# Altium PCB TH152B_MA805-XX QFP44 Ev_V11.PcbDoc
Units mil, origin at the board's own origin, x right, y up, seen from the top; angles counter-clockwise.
Board outline 2850 x 2380 mil, 2 copper layers (Top Layer, Bottom Layer); 48 components, 65 nets, 282 pads, 145 vias.
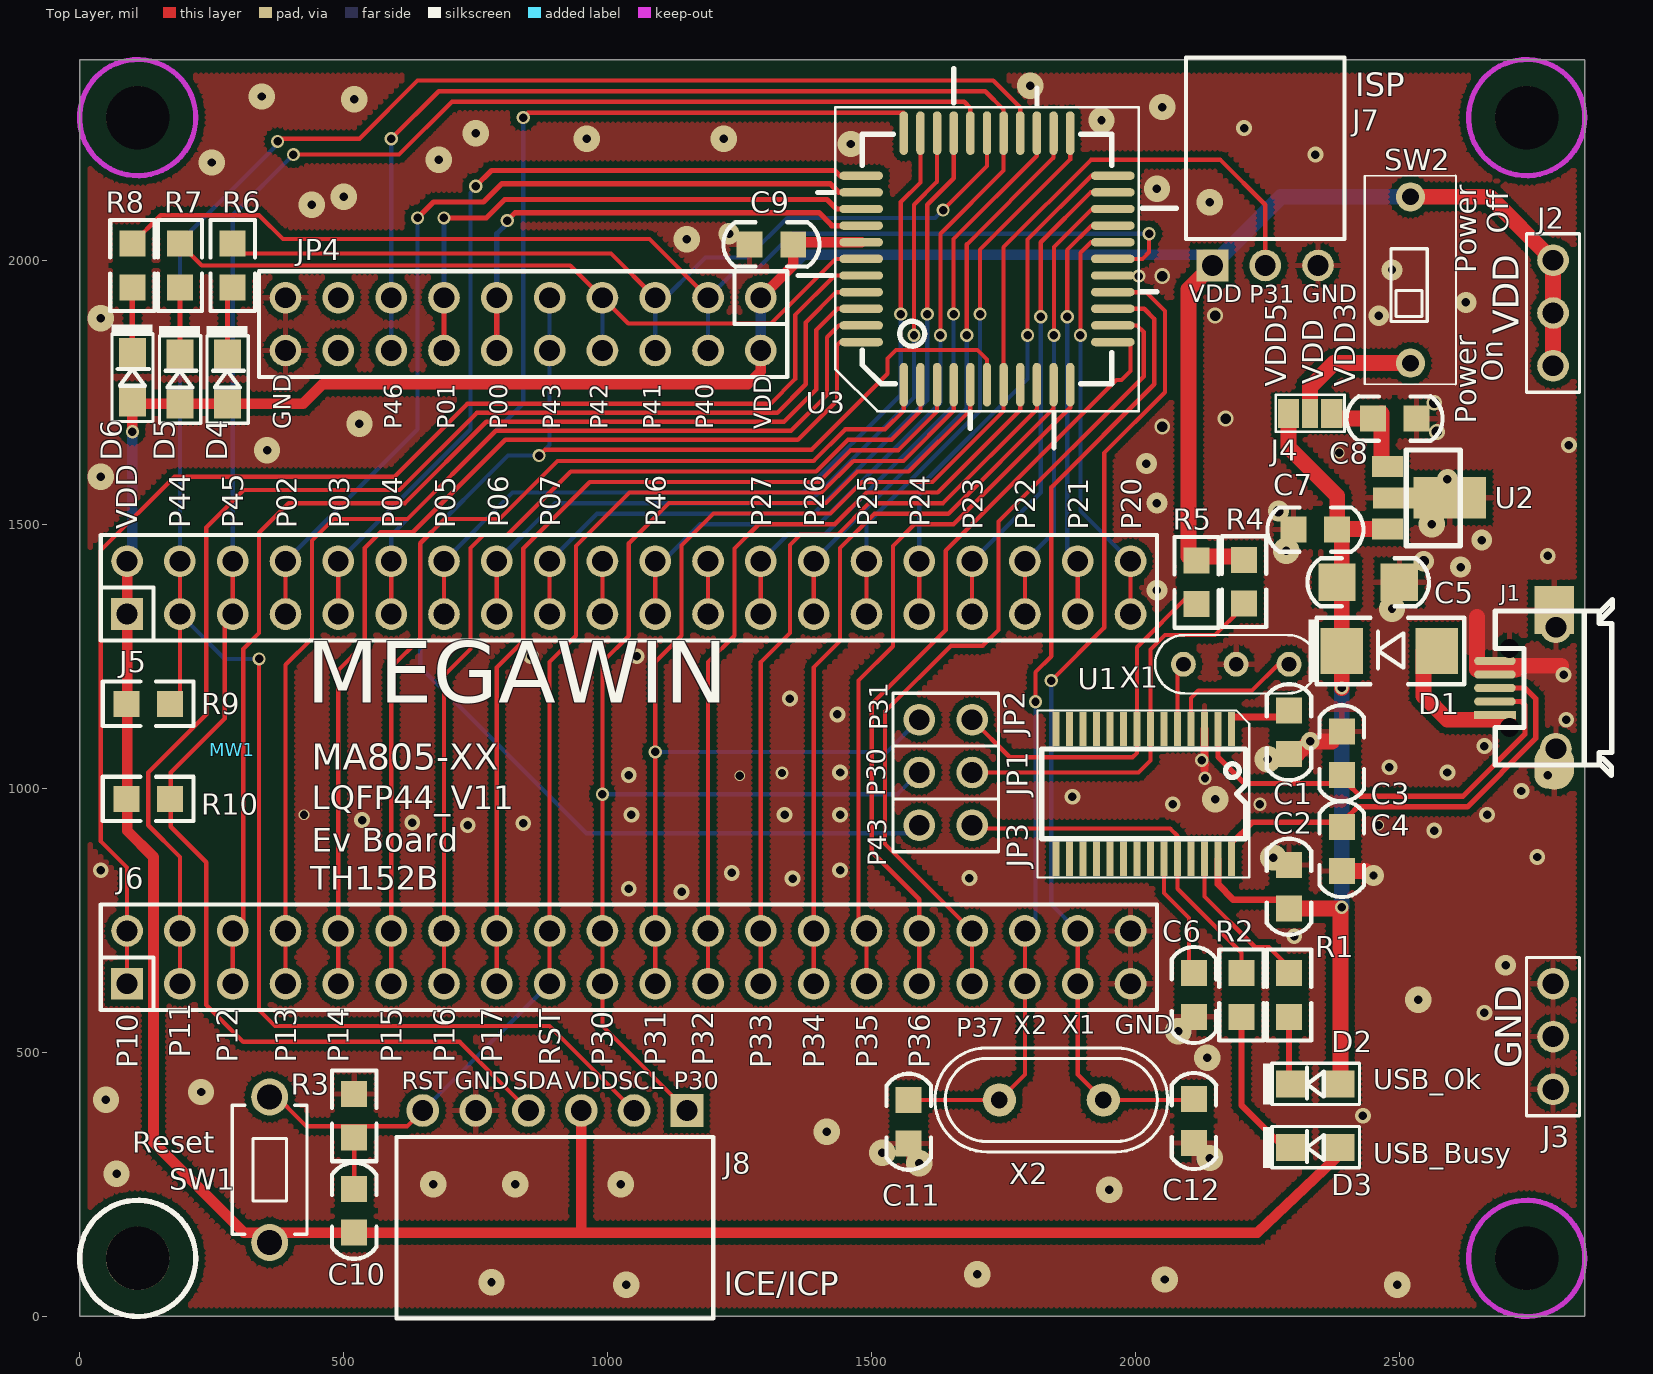
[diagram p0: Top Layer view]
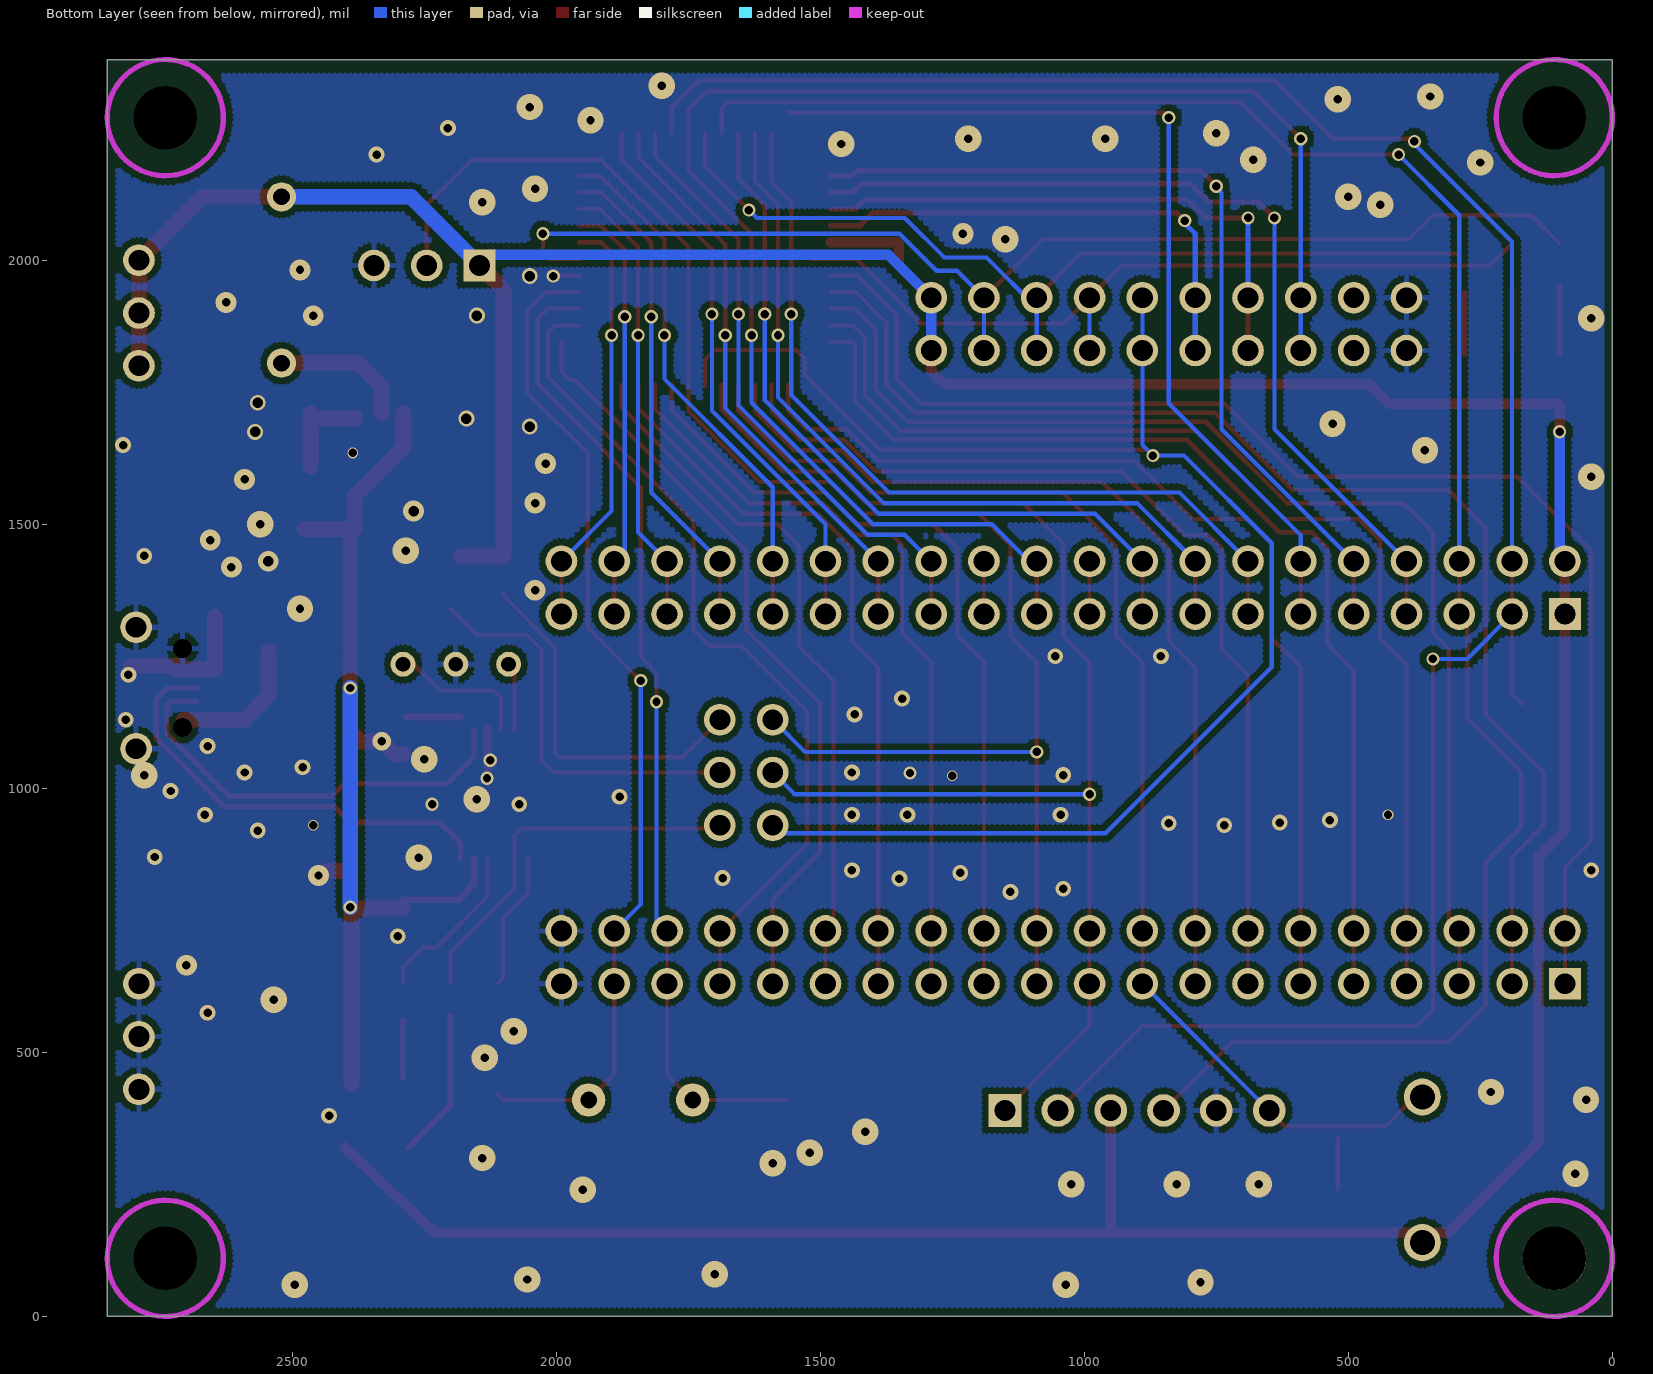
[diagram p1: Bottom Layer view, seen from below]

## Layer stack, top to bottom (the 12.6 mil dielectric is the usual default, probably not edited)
Top Layer: signal copper 1.4
Dielectric: dielectric 12.6, FR-4, Dk 4.8
Bottom Layer: signal copper 1.4

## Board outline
0,0 0,2380 2850,2380 2850,0

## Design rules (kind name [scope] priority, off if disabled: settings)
Clearance 12 [All] p1 off: gap=12
Clearance 10 [All] p2 off: gap=10
Clearance 6 [All] p3: gap=6
ComponentClearance [All] p1 off: gap=10 collisioncheckmode=3 verticalgap=10 showdistances=FALSE
HoleSize [All] p1: absolutevalues=TRUE maxlimit=500 minlimit=1 maxpercent=80.000 minpercent=20.000
MinimumSolderMaskSliver [All] p1 off: minsoldermaskwidth=10
PolygonConnect VIA [ISVIA] p1: connectstyle=Direct reliefconductorwidth=10 reliefentries=4 polygonreliefangle="90 Angle"
PolygonConnect [All] p2: connectstyle=Relief reliefconductorwidth=10 reliefentries=4 polygonreliefangle="90 Angle"
RoutingVias [All] p1: holewidth=16 width=25 viastyle="Through Hole" minholewidth=16 minwidth=24 maxholewidth=28 maxwidth=50
SilkToSilkClearance [All] p1 off: silktosilkclearance=10
SilkscreenOverComponentPads [All] p1 off: minsilkscreentomaskgap=10
SolderMaskExpansion [All] p1 off: expansion=4
Width [All] p1: maxlimit=200 minlimit=6 preferedwidth=10
23 further rules are at their usual default settings.

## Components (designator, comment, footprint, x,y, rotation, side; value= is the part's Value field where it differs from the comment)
C1 "4.7uF" 0805C 2290,1106.34 r270 top
C2 "0.1uF" 0805C 2290,813.66 r270 top
C3 "15pF" 0805C 2390,1066.34 r90 top
C4 "15pF" 0805C 2390,885 r270 top
C5 "4.7uF" 1206C 2440,1390 r0 top
C6 "0.1uF" 0805C 2110,608.66 r90 top
C7 "0.1uF" 0805C 2340,1490 r180 top
C8 "4.7uF" 0805C 2490,1700 r0 top
C9 "0.1uF" 0805C 1310,2030 r180 top
C10 "1u" 0805C 520,200 r90 top
C11 "NC" 0805C 1570,368.66 r270 top
C12 "NC" 0805C 2110,370 r270 top
D1 "1N5817" D5817_SMD_1 2480,1260 r0 top
D2 "Yellow" 0805D 2340,440 r180 top
D3 "RED" 0805D 2340,320 r180 top
D4 "Green" 0805D 280,1775 r90 top
D5 "RED" 0805D 190,1775 r90 top
D6 "Green" 0805D 100,1778.08 r90 top
J1 "Micro USB母座" JACK_USB_SMD290X220P065 2680,1190 r180 top
J2 "*" PS3P254 2790,1800 r90 top
J3 "*" PS3P254 2790,430 r90 top
J4 "*" JUMP3_SMD 2330,1710 r0 top
J5 "*" PS20X2P254 90,1330 r0 top locked
J6 "*" PS20X2P254 90,630 r0 top
J7 "*" PS3P254f_90 2145,1990 r0 top
J8 "*" PS6P254F_90 1150,390 r180 top
JP1 "JUMPER2" PS2P254 1590,1030 r0 top
JP2 "JUMPER2" PS2P254 1590,1130 r0 top
JP3 "JUMPER2" PS2P254 1590,930 r0 top
JP4 "*" PS10X2P254 1290,1929 r180 top
MW1 "MW-A4" MEGAWIN_T 289.19,1073.04 r0 top
R1 "1K" 0805R 2290,608.66 r270 top
R2 "1K" 0805R 2200,608.66 r270 top
R3 "47K" 0805R 520,380 r270 top
R4 "4.7K" 0805R 2205,1391.34 r270 top
R5 "4.7K" 0805R 2115,1390 r270 top
R6 "1K" 0805R 290,1990 r270 top
R7 "1K" 0805R 190,1990 r270 top
R8 "1K" 0805R 100,1990 r270 top
R9 "4.7K" 0805R 130,1160 r180 top
R10 "4.7K" 0805R 130,980 r180 top
SW1 "SW TACT-SPST" SW_T_2P 360,277.79 r90 top
SW2 "-" DIP2_SW 2520,1805.04 r90 top
U1 "MA101_TSSOP28" TSSOP28_170P065 2014.84,989.52 r180 top
U2 "AIC1734-33(SOT-89)" SOT89 2476.38,1550 r270 top
U3 "MA805-XX  LQFP44" QFP44_10X10P080 1560.71,1764.31 r90 top locked
X1 "6MHz" X3P 2290,1235 r180 top
X2 "NC" X49U 1840,410 r0 top

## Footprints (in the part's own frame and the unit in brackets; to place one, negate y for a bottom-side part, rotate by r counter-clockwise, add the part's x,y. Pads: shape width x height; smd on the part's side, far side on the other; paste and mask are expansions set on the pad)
0805C [mm]
  rect 1.25x1.25 smd: 1(-1.05,0) 2(1.05,0)
  silkscreen extent -2.31,-1.07 2.31,1.07
0805D [mm]
  rect 1.4x1.3 smd: 1(-1.192,0) 2(1.192,0)
  silkscreen extent -2.12,-1 2.53,0.98
0805R [mm]
  rect 1.25x1.25 smd: 1(-1.05,0) 2(1.05,0)
  silkscreen extent -2.18,-1.07 2.18,1.07
1206C [mm]
  rect 1.8x1.8 smd: 1(-1.5,0) 2(1.5,0)
  silkscreen extent -2.92,-1.15 2.92,1.16
D5817_SMD_1 [mil]
  rect 80x86.61 smd: 1(90,0) 2(-90,0)
  silkscreen extent -153,-63 142,63
DIP2_SW [mm]
  round 1.4 hole 0.8: 1(0,0) 2(8,0)
  silkscreen extent -1.02,-2.2 9.02,2.2
JACK_USB_SMD290X220P065 [mm]
  rect 1.9x1.8 on Mech2: 0(-2.85,-1.15) 0(-2.85,1.15)
  round 0.8 hole 0.9 unplated: 1(-0.7,1.9) 5(-0.7,-1.9)
  rect 2x0.4 smd: 1(0,1.3)
  oval 2x0.4 smd: 2(0,0.65) 3(0,0) 4(0,-0.65) 5(0,-1.3)
  round 1.524 hole 1: 5(-2.931,2.921) 5(-2.931,-2.921)
  oval 1.9x2.3 smd: 5(-2.85,3.75)
  rect 1.9x2.3 smd: 5(-2.85,-3.75)
  silkscreen extent -5.65,-4.25 -0.01,4.2
JUMP3_SMD [mil]
  rect 40x55 smd: 1(-41,0) 3(41,0)
  rect 30x55 smd: 2(0,0)
  silkscreen extent -65,-35 65,35
MEGAWIN_T [mil]
PS2P254 [mil]
  round 60 hole 39.37: 1(0,0) 2(100,0)
  silkscreen extent -50,-50 150,50
PS3P254 [mil]
  round 60 hole 39.37: 1(0,0) 2(100,0) 3(200,0)
  silkscreen extent -50,-50 250,50
PS3P254f_90 [mil]
  rect 60x60 hole 39.37: 1(0,0)
  round 60 hole 39.37: 2(100,0) 3(200,0)
  silkscreen extent -50,50 250,394
PS6P254F_90 [mil]
  rect 62x62 hole 39.37: 1(0,0)
  round 62 hole 39.37: 2(100,0) 3(200,0) 4(300,0) 5(400,0) 6(500,0)
  silkscreen extent -50,50 550,394
PS10X2P254 [mil]
  round 60 hole 39.37: 1(0,0) 2(0,100) 3(100,0) 4(100,100) 5(200,0) 6(200,100) 7(300,0) 8(300,100) 9(400,0) 10(400,100) 11(500,0) 12(500,100) 13(600,0) 14(600,100) 15(700,0) 16(700,100) 17(800,0) 18(800,100) 19(900,0) 20(900,100)
  silkscreen extent -50,-50 950,150
PS20X2P254 [mil]
  rect 60x60 hole 39.37: 1(0,0)
  round 60 hole 39.37: 2(0,100) 3(100,0) 4(100,100) 5(200,0) 6(200,100) 7(300,0) 8(300,100) 9(400,0) 10(400,100) 11(500,0) 12(500,100) 13(600,0) 14(600,100) 15(700,0) 16(700,100) 17(800,0) 18(800,100) 19(900,0) 20(900,100) 21(1000,0) 22(1000,100) 23(1100,0) 24(1100,100) 25(1200,0) 26(1200,100) 27(1300,0) 28(1300,100) 29(1400,0) 30(1400,100) 31(1500,0) 32(1500,100) 33(1600,0) 34(1600,100) 35(1700,0) 36(1700,100) 37(1800,0) 38(1800,100) 39(1900,0) 40(1900,100)
  silkscreen extent -50,-50 1950,150
QFP44_10X10P080 [mm]
  oval 2.1x0.406 smd: 1(0,0) 2(0,-0.8) 3(0,-1.6) 4(0,-2.4) 5(0,-3.2) 6(0,-4) 7(0,-4.8) 8(0,-5.6) 9(0,-6.4) 10(0,-7.2) 11(0,-8) 23(12.1,-8) 24(12.1,-7.2) 25(12.1,-6.4) 26(12.1,-5.6) 27(12.1,-4.8) 28(12.1,-4) 29(12.1,-3.2) 30(12.1,-2.4) 31(12.1,-1.6) 32(12.1,-0.8) 33(12.1,0)
  oval 0.406x2.1 smd: 12(2.05,-10.05) 13(2.85,-10.05) 14(3.65,-10.05) 15(4.45,-10.05) 16(5.25,-10.05) 17(6.05,-10.05) 18(6.85,-10.05) 19(7.65,-10.05) 20(8.45,-10.05) 21(9.25,-10.05) 22(10.05,-10.05) 34(10.05,2.05) 35(9.25,2.05) 36(8.45,2.05) 37(7.65,2.05) 38(6.85,2.05) 39(6.05,2.05) 40(5.25,2.05) 41(4.45,2.05) 42(3.65,2.05) 43(2.85,2.05) 44(2.05,2.05)
  silkscreen extent -3.04,-13.12 15.19,5.08
SOT89 [mm]
  rect 1.016x1.5 smd: 1(-1.5,0) 3(1.5,0)
  rect 2x3.5 smd: 2(0,3)
  rect 1.016x2.6 smd: 2(0,0.6)
  silkscreen extent -2.3,0.9 2.3,3.5
SW_T_2P [mil]
  round 70 hole 47.24: 1(-137.79,0) 2(137.79,0)
  silkscreen extent -122,-71 122,71
TSSOP28_170P065 [mil]
  rect 13x65 smd: 1(-166.34,-123) 2(-140.75,-123) 3(-115.16,-123) 4(-89.57,-123) 5(-63.98,-123) 6(-38.39,-123) 7(-12.79,-123) 8(12.8,-123) 9(38.39,-123) 10(63.98,-123) 11(89.57,-123) 12(115.16,-123) 13(140.75,-123) 14(166.34,-123) 15(166.34,123) 16(140.75,123) 17(115.16,123) 18(89.57,123) 19(63.98,123) 20(38.39,123) 21(12.8,123) 22(-12.79,123) 23(-38.39,123) 24(-63.98,123) 25(-89.57,123) 26(-115.16,123) 27(-140.75,123) 28(-166.34,123)
  silkscreen extent -200,-158 201,158
X3P [mm]
  round 1.2 hole 0.711: 1(0,0) 2(5.08,0) 3(2.54,0)
  silkscreen extent -1.36,-1.4 6.44,1.4
X49U [mm]
  round 1.6 hole 0.8: 1(-2.5,0) 2(2.5,0)
  silkscreen extent -5.6,-2.5 5.6,2.5

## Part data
C1 C5 C8: library part CAP
C2 C3 C4 C6 C7 C9: library part "CAP NP"
C10: library part C
C11 C12: library part "C NP"
D1: library part DIODE_ZD, "Schottky Diode"
D2 D3 D4 D5 D6: library part LED
J1: library part CON5, "Connector"
J2 J3 J4 J7: library part CON3
J5 J6: library part CON40A
J8: library part CON6
JP4: library part CON10X2
R1 R2 R4 R5 R6 R7 R8: library part R_Dup1
R3 R9 R10: library part R
SW2: library part SW-2
U2: library part AIC1734-33(SOT-89)_0
U3: library part IC44_A
X1: library part CRYSTAL_RC
X2: library part CRYSTAL

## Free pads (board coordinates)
  round 120 hole 120 unplated: 0(110,110)
  round 118.11 hole 120 unplated: 0(110,2270) 0(2740,110) 0(2740,2270)

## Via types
v1: diameter 50, hole 16, Top Layer to Bottom Layer, tented both sides, 46 vias
v2: diameter 30, hole 16, Top Layer to Bottom Layer, tented both sides, 38 vias
v3: diameter 25, hole 16, Top Layer to Bottom Layer, tented both sides, 36 vias
v4: diameter 39.37, hole 16, Top Layer to Bottom Layer, tented both sides, 11 vias
v5: diameter 30, hole 20, Top Layer to Bottom Layer, tented both sides, 6 vias
v6: diameter 20, hole 16, Top Layer to Bottom Layer, tented both sides, 4 vias
v7: diameter 39.37, hole 20, Top Layer to Bottom Layer, tented both sides, 2 vias
v8: diameter 40, hole 16, Top Layer to Bottom Layer, tented both sides, 1 vias
v9: diameter 35, hole 16, Top Layer to Bottom Layer, tented both sides, 1 vias

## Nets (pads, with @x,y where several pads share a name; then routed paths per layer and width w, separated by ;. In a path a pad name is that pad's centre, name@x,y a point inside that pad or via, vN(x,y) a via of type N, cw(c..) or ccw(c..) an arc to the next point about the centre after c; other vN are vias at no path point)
D+: C4.1 J1.3 U1.28 | length 827.6
  Top Layer w10: U1.28 2181.18,896.18 2220.67,935.67 C4.1@2390,935.67 ; C4.1@2405,950 2420,965 2627.72,965 2757,1094.28 2757,1169.93 2736.93,1190 J1.3
D-: C3.1 J1.2 U1.2 | length 819.3
  Top Layer w10: U1.2 2155.59,1059.41 2205.63,1009.37 C3.1@2390,1009.37 ; C3.1@2400,1010 2425,985 2619.44,985 2737,1102.56 2737,1157.84 2730.43,1164.41 J1.2
GND_POWER: C1.2 C2.1 C3.2 C4.2 C5.2 C6.1 C7.2 C8.2 C9.2 C11.2 C12.2 J1.4 J1.5 J3.1 J3.2 J3.3 J6.39 J6.40 J7.3 J8.5 JP4.19 JP4.20 R3.1 U1.3 U2.2 U3.16 X1.3 | length 557.6
  Top Layer w10: U3.16 2004.7,1971.01 v3(2005.71,1970)
  Top Layer w15: 2130,1036 v3@2130,1046 ; U1.3 v3@2130,1046 ; v3@2131,1045 v3@2130,1046
  Top Layer w30: C1.2 2306,1065 v9(2330,1089) 2371.32,1089 C3.2 ; C4.2 v4@2434.66,843.66 ; 2645.87,1225.05 2719.29,1225.05 ; 2645.87,1227.64 2645.87,1324.72 ; 2708.54,1232.05 2805.63,1232.05
  other v1: 1035,60 2495,60 780,65 2055,70 1700,80 1950,240 670,250 825,250 1025,250 70,270 1590,290 2140,300 1520,310 1415,350 50,410 230,425 2135,490 2080,540 2535,600 2260,869 2150,979 2780,1025 2250,1055 2485,1340 2285,1450 2560,1500 40,1590 355,1640 530,1690 40,1890 1150,2040 440,2105 2140,2110 500,2120 2040,2135 250,2185 680,2190 1460,2220 960,2230 1220,2230 750,2240 1935,2265 2050,2290 520,2305 345,2310 1800,2330
  other v2: 2430,380 2660,575 2300,720 1140,804 1040,810 1350,829 1685,830 1235,840 40,845 1440,845 2760,870 2565,920 735,930 840,934 630,935 535,940 1045,950 1335,950 1440,950 2665,950 2070,970 1880,984 2730,995 1040,1025 1440,1030 2590,1030 2480,1040 2660,1080 2815,1130 1435,1140 1345,1170 2810,1215 855,1250 1055,1250 2780,1440 2820,1650 2340,2200 2205,2250
  other v3: 2235,970 2131,1019 1330,1029 2125,1053
  other v4: 2700,665 2450,835 2040,1375 2615,1419 2655,1470 2040,1540 2590,1585 2020,1615 2460,1895 2625,1920 2485,1981.57
  other v5: 2570,1675 2050,1685 2170,1700 2565,1730 2150,1895 2050,1970
  other v6: 2460,930 425,950 1250,1024 2385,1635
  other v7: 2545,1430 2270,1525
  other v8: 1230,2050
MA101_RX: JP2.2 R5.2 U1.8 | length 686.1
  Top Layer w8: JP2.2 1761.15,1058.85 1993.85,1058.85 2002.05,1067.05 U1.8 2002.05,1267.05 2100,1365 R5.2@2100,1367.66
MA101_TX: JP1.2 R4.2 U1.7 | length 761.4
  Top Layer w8: JP1.2 2005,1030 2027.64,1052.64 2027.64,1262.64 2055.12,1290.12 2150.12,1290.12 R4.2@2200,1340
NetC1_1: C1.1 U1.1 | length 102.5
  Top Layer w13: U1.1@2181.18,1135 C1.1@2283.66,1135
NetC6_2: C6.2 U1.23 | length 258.7
  Top Layer w8: U1.23 2053.23,801.77 2100.67,754.33 2100.67,640.67 C6.2@2110,631.34
NetD1_1: D1.1 J1.1 | length 263.6
  Top Layer w30: D1.1@2545,1260 2545,1175 2590,1130 J1.1@2705,1130
NetD2_2: D2.2 R1.2 | length 107.3
  Top Layer w12: D2.2@2290,452.68 R1.2@2290,560
NetD3_2: D3.2 R2.2 | length 280.5
  Top Layer w12: R2.2 2200,400 D3.2@2280,320
NetD4_2: D4.2 R6.2 | length 116.7
  Top Layer w10: D4.2 R6.2@280,1938.66
NetD5_2: D5.2 R7.2 | length 126.7
  Top Layer w10: D5.2 R7.2
NetD6_2: D6.2 R8.2 | length 123.7
  Top Layer w10: D6.2 R8.2
NetJ4_2: J4.2 SW2.1 | length 258.7
  Top Layer w30: J4.2 2330,1760 2375.04,1805.04 SW2.1
NetJ5_19: J5.19 J5.20 | length 100
  Top Layer w8: J5.19 J5.20
NetJ5_23: J5.23 J5.24 | length 100
  Top Layer w8: J5.23 J5.24
NetU1_4: U1.4 X1.1 | length 270.8
  Top Layer w8: U1.4 2104.41,1171.29 2118.12,1185 2220,1185 2270,1235 X1.1
NetU1_5: U1.5 X1.2 | length 127.1
  Top Layer w8: U1.5 2078.82,1223.82 X1.2
P00: JP4.11 JP4.12 U3.37 | length 1044.6
  Top Layer w10: JP4.12@790,1820 JP4.12 JP4.11 ; v3(810,2075) 825,2090 1400,2090 1424.5,2065.5 U3.37
  Bottom Layer w10: JP4.12 JP4.11 790,2050 v3@810,2070
P01: JP4.13 JP4.14 U3.36 | length 1063
  Top Layer w10: JP4.14 JP4.13 ; v3(690,2080) 770,2080 805,2115 1415,2115 1433.01,2096.99 U3.36
  Bottom Layer w10: JP4.13 v3(690,2080)
P02: J5.7 J5.8 U3.35 | length 1727.3
  Top Layer w8: J5.7 J5.8
  Top Layer w10: v3(640,2080) 670,2110 765,2110 800,2145 1421.17,2145 1437.68,2128.49 U3.35
  Bottom Layer w8: J5.8 640,1680 v3(640,2080)
P03: J5.9 J5.10 U3.34 | length 1663.6
  Top Layer w8: J5.9 J5.10
  Top Layer w10: v3(750,2140) 780,2170 1430,2170 1440.02,2159.98 U3.34
  Bottom Layer w8: J5.10 740,1680 740,2127.62 v3@751.19,2138.81
P04: J5.11 J5.12 U3.33 | length 1767.3
  Top Layer w8: J5.11 J5.12 ; v3(840,2270) 849,2279 U3.33@1560,2279
  Bottom Layer w8: J5.12 590,1479 840,1729 v3(840,2270)
P05: J5.13 J5.14 U3.32 | length 1606.6
  Top Layer w8: J5.13 J5.14 ; v3(1555,1898) 1555,2110 1592.21,2147.21 U3.32
  Bottom Layer w8: J5.14 820,1560 1370,1560 1555,1745 v3(1555,1898)
P06: J5.15 J5.16 U3.31 | length 1537.2
  Top Layer w8: J5.15 J5.16 ; v3(1580,1858) 1580,2105 1623.7,2148.7 U3.31
  Bottom Layer w8: J5.16 900,1540 1380,1540 1580,1740 v3(1580,1858)
P07: J5.17 J5.18 U3.30 | length 1467.8
  Top Layer w8: J5.17 J5.18 ; v3(1605,1898) 1605,2105 1655.2,2155.2 U3.30
  Bottom Layer w8: J5.18 980,1520 1390,1520 1605,1735 v3(1605,1898)
P10: J6.1 J6.2 U3.40 | length 2567.4
  Top Layer w8: J6.1 J6.2 90,850 40,900 40,1450 180,1590 596,1590 734,1728 1308,1728 1355,1775 1355,1896 1430.01,1971.01 U3.40
P11: J6.3 J6.4 U3.41 | length 2427.5
  Top Layer w8: J6.3 J6.4 190,870 130,930 130,1030 240,1140 240,1494 311,1565 606,1565 752,1711 1321,1711 1375,1765 1375,1882 1432.51,1939.51 U3.41
P12: J6.5 J6.6 U3.42 | length 2301.5
  Top Layer w8: J6.5 290,720 310,740 310,1264 340,1294 340,1344 ; 340,1299 340,1344 ; U3.42 1435.02,1908.02 1395,1868 1395,1755 1334,1694 770,1694 616,1540 396,1540 340,1484 340,1344
P13: J6.7 J6.8 U3.43 | length 2147.4
  Top Layer w8: J6.7 J6.8 390,1234 440,1284 440,1329 ; 440,1314 440,1329 ; U3.43 1437.52,1876.52 1415,1854 1415,1745 1347,1677 788,1677 621,1510 481,1510 440,1469 440,1329
P14: J6.9 J6.10 U3.44 | length 2083.8
  Top Layer w8: J6.9 J6.10 490,1224 540,1274 540,1359 ; 540,1284 540,1359 ; U3.44 1440.02,1845.02 1434,1839 1434,1734 1360,1660 806,1660 631,1485 570,1485 540,1455 540,1359
P15: J6.11 J6.12 U3.1 | length 1925.4
  Top Layer w8: J6.11 J6.12 590,1229 645,1284 645,1464 691,1510 795,1510 905,1620 1390,1620 1450,1680 1525,1680 1560.71,1715.71 U3.1
P16: J6.13 J6.14 U3.2 | length 1874.9
  Top Layer w8: J6.13 J6.14 690,1214 740,1264 740,1319 ; 740,1299 740,1319 ; U3.2 1592.21,1715 1537.21,1660 1455,1660 1395,1600 930,1600 809.91,1479.91 764.91,1479.91 740,1455 740,1319
P17: J6.15 J6.16 U3.3 | length 1894.9
  Top Layer w8: J6.15 J6.16 790,1229 840,1279 840,1354 ; 840,1289 840,1354 ; 1623.7,1720.99 U3.3 1623.7,1713.7 1550,1640 1460,1640 1400,1580 966,1580 840,1454 840,1354
P20: J5.39 J5.40 U3.18 | length 793
  Top Layer w8: v3(1895,1858) 1895,2014 1915,2034 U3.18 ; J5.39 J5.40
  Bottom Layer w8: v3(1895,1858) 1895,1525 J5.40
P21: J5.37 J5.38 U3.19 | length 802.9
  Top Layer w8: v3(1870,1893) 1870,2019 1916.5,2065.5 U3.19 ; J5.37 J5.38
  Bottom Layer w8: v3(1870,1893) 1870,1450 J5.38
P22: J5.35 J5.36 U3.20 | length 859.2
  Top Layer w8: J5.35 J5.36 ; v3(1845,1858) 1845,2025 1916.99,2096.99 U3.20
  Bottom Layer w8: J5.36 1845,1485 v3(1845,1858) v3@1845.19,1857.81
P23: J5.33 J5.34 U3.21 | length 933.4
  Top Layer w8: J5.33 J5.34 ; v3(1820,1893) 1820,2034 1914.49,2128.49 U3.21
  Bottom Layer w8: J5.34 1820,1560 v3(1820,1893)
P24: J5.31 J5.32 U3.22 | length 1005.4
  Top Layer w8: J5.31 J5.32 ; v3(1795,1858) 1795,2039 1915.98,2159.98 U3.22
  Bottom Layer w8: J5.32 1590,1570 1795,1775 v3(1795,1858)
P25: J5.29 J5.30 U3.23 | length 1070.4
  Top Layer w8: J5.29 J5.30 ; v3(1705,1898) 1705,2020 1875.67,2190.67 U3.23
  Bottom Layer w8: J5.30 1490,1500 1705,1715 v3(1705,1898)
P26: J5.27 J5.28 U3.24 | length 1098.8
  Top Layer w8: J5.27 J5.28 ; v3(1680,1858) 1680,2030 1844.17,2194.17 U3.24
  Bottom Layer w8: J5.28 1680,1720 v3(1680,1858)
P27: J5.25 J5.26 U3.25 | length 1168.2
  Top Layer w8: J5.25 J5.26 ; v3(1655,1898) 1655,2040 1812.68,2197.68 U3.25
  Bottom Layer w8: J5.26 1340,1480 1410,1480 1655,1725 v3(1655,1898)
P30_RXD: J6.19 J6.20 J8.1 JP1.1 U3.5 | length 2617
  Top Layer w8: 1040,1304 1040,1344 ; J8.1 990,550 J6.19 J6.20 v3(990,989) 990,1239 1040,1289 1040,1344 ; U3.5 1686.69,1716.69 1570,1600 1473.14,1600 1413.35,1540.21 1116.21,1540.21 1040,1464 1040,1344
  Bottom Layer w8: v3(990,989) 1549,989 JP1.1
P31_TXD: J6.21 J6.22 J7.2 JP2.1 U3.7 | length 3141.2
  Top Layer w8: J6.21@1090,639 J6.22 v3(1090,1069) 1090,1239 1140,1289 1140,1319 ; 1140,1294 1140,1319 ; J7.2@2245,1980 J7.2 2245,2105 2160,2190 1915,2190 1749.68,2024.69 U3.7 1749.68,1714.69 1615,1580 1481.42,1580 1421.63,1520.21 1200.21,1520.21 1140,1460 1140,1319
  Bottom Layer w8: v3(1090,1069) 1529,1069 JP2.1
P32: J6.23 J6.24 U3.8 | length 1533.6
  Top Layer w8: J6.23@1190,639 J6.24 1190,1239 1240,1289 1240,1454 1286,1500 1430,1500 1490,1560 1625,1560 1781.18,1716.18 U3.8
P33: J6.25 J6.26 U3.9 | length 1465.2
  Top Layer w8: J6.25@1290,639 J6.26 1290,1239 1345,1294 1345,1460.71 1364.29,1480 1435,1480 1495,1540 1635,1540 1812.68,1717.68 U3.9
P34: J6.27 J6.28 U3.10 | length 1395.5
  Top Layer w8: J6.27@1390,639 J6.28 1390,1229 1440,1279 1440,1455 1505,1520 1645,1520 1844.17,1719.17 U3.10
P35: J6.29 J6.30 U3.11 | length 1326.7
  Top Layer w8: J6.30@1470,740 1475,745 1475,1204 1540,1269 1540,1459 1581,1500 1655,1500 1875.67,1720.67 U3.11 ; J6.29@1490,639 J6.30
P36: J6.31 J6.32 U3.12 | length 1452.1
  Top Layer w8: J6.31@1590,639 J6.32 1590,790 1500,880 1500,1160 1640,1300 1640,1450 1963.05,1773.05 1973.05,1773.05 1990,1790 U3.12@1990,1845
P37: J6.33 J6.34 U3.13 | length 1605
  Top Layer w8: J6.33@1690,639 J6.34 1525.32,894.68 1525.32,1145.32 1650,1270 1710,1270 1740,1300 1740,1399 ; 1740,1389 1740,1399 ; U3.13 2002.48,1876.52 2015,1864 2015,1780 1740,1505 1740,1399
P40: JP4.3 JP4.4 R8.1 U3.17 | length 2305.9
  Top Layer w8: R8.1 153.66,2085 340,2085 385,2040 1079,2040 JP4.3 ; U3.17@1991.5,2002.5 U3.17 2012.5,2002.5 2025,2015 v3(2025,2050)
  Bottom Layer w8: JP4.4 JP4.3 1241,1980 1280,1980 1350,2050 v3(2025,2050)
P41: JP4.5 JP4.6 R6.1 U3.28 | length 1750.7
  Top Layer w8: R6.1@290,2012.68 1006.32,2012.68 JP4.5 ; v3(1635,2095) 1718.19,2178.19 U3.28 U3.28@1718.19,2208.19
  Bottom Layer w8: JP4.6 JP4.6@1090,1830 ; JP4.6@1090.5,1829.5 JP4.6@1090,1830 ; v3(1635,2095) 1620,2080 1340,2080 1265,2005 1185,2005 1090,1910 JP4.6@1090,1830
P42: JP4.7 JP4.8 R7.1 U3.39 | length 1553.6
  Top Layer w8: R7.1@190,2011.34 R7.1@190,2025 ; R7.1 231.34,1990 929,1990 JP4.7 1039,1880 1308.99,1880 1431.5,2002.5 U3.39 U3.39@1516.5,2002.5
  Bottom Layer w8: JP4.8 JP4.7
P43: JP3.1 JP4.9 JP4.10 U3.6 | length 2923.2
  Top Layer w8: v3(870,1630) 881.21,1641.21 1386.21,1641.21 1530,1785 1530,1814 1546,1830 1700,1830 1718.19,1811.81 U3.6 U3.6@1718.19,1761.9
  Bottom Layer w8: JP4.9@890,1930 JP4.9 JP4.10 890,1650 v3(870,1630) 811.01,1630 645,1463.99 645,1230 960,915 1575,915 JP3.1
P44: J5.3 J5.4 J8.2 R9.1 U3.26 | length 4311.4
  Top Layer w8: R9.1 190,1178.66 J5.3 J5.4 ; v3(340,1245) 340,580 370,550 890,550 J8.2 ; v3@375,2230 530,2230 640,2340 1730,2340 1781.18,2288.82 U3.26
  Bottom Layer w8: J5.3 275,1245 v3(340,1245) ; J5.4 190,2035 v3@380,2225
  other v3: 375,2225
P45: J5.5 J5.6 J8.4 R10.1 U3.29 | length 3802.5
  Top Layer w8: J5.6 J5.5 275,1315 275,1132.32 172.68,1030 172.68,927.32 240,860 240,590 310,520 720,520 J8.4 ; v3(405,2200) 605,2200 705,2300 1675,2300 1686.69,2288.31 U3.29
  Bottom Layer w8: J5.6 290,2085 v3(405,2200)
P46: J5.21 J5.22 JP4.15 JP4.16 U3.27 | length 2981.5
  Top Layer w8: v3(590,2230) 680,2320 1715,2320 1749.68,2285.31 U3.27 1749.68,2169.69 1630,2050 v3(1630,1858) ; J5.21 J5.22
  Bottom Layer w8: JP4.16 JP4.15 v3(590,2230) ; J5.22 1105,1430 1175,1500 1400,1500 1630,1730 v3(1630,1858)
P60: C11.1 J6.35 J6.36 U3.14 X2.1 | length 1859
  Top Layer w8: C11.1@1561.34,410 C11.1 X2.1 1790,458.42 J6.35 J6.36 ; v3(1810,1164) 1810,1220 1840,1250 1840,1570 2035,1765 2035,1889 2015.98,1908.02 U3.14
  Bottom Layer w8: J6.36@1810,730 v3(1810,1164)
P61: C12.1 J6.37 J6.38 U3.15 X2.2 | length 1912.9
  Top Layer w8: v3@1840,1199 v3(1840,1204) 1940,1304 1940,1635 2055,1750 2055,1904 2019.49,1939.51 U3.15 ; J6.38 J6.37 1890,458.42 X2.2 2100,410 C12.1@2110,420
  Bottom Layer w8: v3@1840,1199 1840,780 J6.38
RST: C10.2 J6.17 J6.18 J8.6 R3.2 SW1.2 U3.4 | length 2488.3
  Top Layer w8: SW1.2@360,430 430,360 620,360 J8.6 ; C10.2 R3.2 ; J6.17 J6.18 890,1239 940,1289 940,1459 1041.21,1560.21 1405.06,1560.21 1464.85,1620 1560,1620 1655.2,1715.2 U3.4
  Bottom Layer w8: J8.6 J6.17
USB_BUSY: JP3.2 R2.1 U1.24 | length 799.2
  Top Layer w8: JP3.2@1696,924 1815,924 ; 1750,924 1815,924 ; U1.24@2078.82,883.18 U1.24 ; R2.1@2200,631.34 R2.1 2200,688.82 2078.82,810 U1.24 ; 1815,924 2065,924 2078.82,910.18 U1.24
USB_OK: R1.1 U1.26 | length 316.9
  Top Layer w8: U1.26 2130,795 2226,699 2252.34,699 2290,661.34 R1.1 R1.1@2290,631.34
VDD: C9.1 C10.1 D3.1 D4.1 D5.1 D6.1 J2.1 J2.2 J2.3 J5.1 J5.2 J7.1 J8.3 JP4.1 JP4.2 R4.1 R5.1 R9.2 R10.2 SW1.1 SW2.2 U3.38 | length 8144.8
  Top Layer w20: J5.2 J5.1 90,920 140,870 140,330 311.34,158.66 C10.1 950,158.66 ; v3(100,1675) 100,1725 103.08,1728.08 D5.1 D4.1 423.08,1728.08 460,1765 1265,1765 1290,1790 JP4.2 ; J8.3 950,158.66 ; JP4.1 1351.34,1990.34 C9.1 ; C9.1@1355,2034 U3.38 ; D3.1@2400,320 2393.46,313.46 2393.28,313.29 2230,158.66 950,158.66
  Top Layer w30: J7.1 2100,1945 2100,1439 2180,1439 ; SW2.2 2670,2120 J2.3 J2.2 J2.1
  Bottom Layer w20: J5.2@100,1430 v3(100,1675) ; JP4.2 JP4.1 1371,2010 2125,2010 J7.1
  Bottom Layer w30: J7.1 2275,2120 SW2.2
VDD3: C8.1 J4.3 U2.1 | length 169.6
  Top Layer w30: J4.3@2380,1700 C8.1 ; U2.1@2465,1609.06 C8.1@2465,1710
VDD5: C2.2 C5.1 C7.1 D1.2 D2.1 J4.1 U1.27 U2.3 | length 1676.6
  Top Layer w13: U1.27 2155.59,818.41 2185,789 C2.2@2290,789
  Top Layer w30: J4.1 2289,1646 2381.34,1553.66 C7.1 ; C2.2 2387.32,772.32 D2.1@2387.32,440 ; v3(2390,1190) D1.2@2390,1250 ; D1.2@2390,1270 2390,1481.34 C7.1 ; U2.3 2382.28,1490.94 C7.1
  Bottom Layer w30: v3(2390,775) v3(2390,1190)
pads on no net: J1.0 JP4.17 JP4.18 U1.6 U1.9 U1.10 U1.11 U1.12 U1.13 U1.14 U1.15 U1.16 U1.17 U1.18 U1.19 U1.20 U1.21 U1.22 U1.25

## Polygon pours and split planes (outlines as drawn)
GND_POWER on Bottom Layer "Bottom Layer-No Net" (hatched 90Degree grid 10 track 10, remove dead copper, pour order 1001): 20,20 2830,20 2830,2350 20,2350
GND_POWER on Top Layer "Bottom Layer-No Net" (hatched 90Degree grid 10 track 10, remove dead copper, pour order 1001): 20,20 2830,20 2830,2350 20,2350

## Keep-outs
Keep-Out Layer:
  circle w10: c110,110 r110
  circle w10: c110,2270 r110
  circle w10: c2740,2270 r110
  circle w10: c2740,110 r110

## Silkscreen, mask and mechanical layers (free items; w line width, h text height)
Top Overlay:
  circle w10: c110,110 r110
  text "ISP" at 2415,2310 h45
  text "Off" at 2705,2050 h40 r90
  text "Power" at 2645,1975 h40 r90
  text "VDD" at 2100,1920 h33
  text "GND" at 2315,1920 h33
  text "P31" at 2215,1919 h33
  text "VDD" at 2725,1860 h50 r90
  text "On" at 2695,1770 h40 r90
  text "VDD" at 2355,1765 h40 r90
  text "VDD5" at 2285,1760 h40 r90
  text "VDD3" at 2415,1760 h40 r90
  text "Power" at 2645,1690 h40 r90
  text "GND" at 400,1680 h33 r90
  text "P46" at 610,1680 h33 r90
  text "P01" at 710,1680 h33 r90
  text "P00" at 810,1680 h33 r90
  text "P43" at 910,1680 h33 r90
  text "P42" at 1000,1680 h33 r90
  text "P41" at 1100,1680 h33 r90
  text "P40" at 1200,1680 h33 r90
  text "VDD" at 1310,1680 h33 r90
  text "P07" at 910,1495 h38 r90
  text "P46" at 1110,1495 h38 r90
  text "P27" at 1310,1495 h38 r90
  text "P26" at 1410,1495 h38 r90
  text "P25" at 1510,1495 h38 r90
  text "P24" at 1610,1495 h38 r90
  text "P06" at 812,1494 h38 r90
  text "P44" at 210,1492 h40 r90
  text "P45" at 310,1492 h40 r90
  text "P02" at 411,1492 h38 r90
  text "P03" at 511,1492 h38 r90
  text "P04" at 611,1492 h38 r90
  text "P05" at 711,1492 h38 r90
  text "VDD" at 109,1491 h40 r90
  text "P23" at 1710,1490 h38 r90
  text "P22" at 1810,1490 h38 r90
  text "P21" at 1910,1490 h38 r90
  text "P20" at 2010,1490 h38 r90
  text "P31" at 1530,1110 h35 r90
  text "MA805-XX" at 440,1035 h50
  text "P30" at 1525.32,985 h35 r90
  text "LQFP44_V11" at 440,960 h45
  text "Ev Board" at 440,880 h45
  text "P43" at 1527.22,852.78 h35 r90
  text "TH152B" at 437,808 h45
  text "X1" at 1860,535 h35.43
  text "GND" at 1960,535 h35.43
  text "X2" at 1769,534 h35
  text "P37" at 1660,530 h35
  text "P11" at 210,490 h40 r90
  text "P12" at 300,480 h40 r90
  text "P13" at 410,480 h40 r90
  text "P14" at 510,480 h40 r90
  text "P15" at 610,480 h40 r90
  text "P16" at 710,480 h40 r90
  text "P17" at 800,480 h40 r90
  text "RST" at 910,475 h40 r90
  text "P30" at 1010,475 h40 r90
  text "P31" at 1110,475 h40 r90
  text "P32" at 1200,475 h40 r90
  text "P10" at 110,470 h40 r90
  text "P33" at 1310,470 h40 r90
  text "P34" at 1410,470 h40 r90
  text "P35" at 1510,470 h40 r90
  text "P36" at 1610,470 h40 r90
  text "GND" at 2730,470 h50 r90
  text "RST" at 610,430.53 h33
  text "GND" at 710,430.53 h33
  text "SDA" at 820,430.53 h33
  text "VDD" at 920,430.53 h33
  text "SCL" at 1020,430.53 h33
  text "P30" at 1125,430.53 h33
  text "USB_Ok" at 2450,430 h38
  text "Reset" at 100,310 h40
  text "USB_Busy" at 2450,290 h38
  text "ICE/ICP" at 1220,40 h45
Mechanical 1:
  the board outline again, w13

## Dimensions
0,0 to 0,2380 on Top Overlay
0,0 to 2850,0 on Top Overlay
